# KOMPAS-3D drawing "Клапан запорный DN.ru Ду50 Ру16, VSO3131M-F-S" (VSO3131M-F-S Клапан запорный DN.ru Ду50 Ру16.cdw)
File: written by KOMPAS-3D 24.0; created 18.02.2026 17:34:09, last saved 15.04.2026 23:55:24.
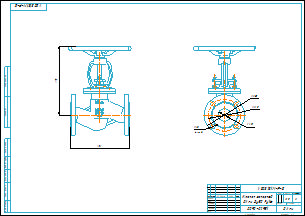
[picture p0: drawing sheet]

Document properties: Автор: R2D2; Форматы листов документа: A2; Полное имя файла: VSO3131M-F-S Клапан запорный DN.ru Ду50 Ру16.m3d; Масса: 10.5; Наименование: Клапан запорный DN.ru Ду50 Ру16; Количество листов документа: 1; Примечание: D090-02952

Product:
- Part/product: Клапан запорный DN.ru Ду50 Ру16  | designation VSO3131M-F-S
    Масса: 10.5
    Раздел спецификации: Прочие изделия
    Примечание: D090-02952

Views: Вид 1, Спереди, Проекционный вид 2
Referenced files in E:\Работа\Зайцев\VSO3131M-F-S Клапан запорный DN.ru Ду15-100 Ру40\DN50\: VSO3131M-F-S Клапан запорный DN.ru Ду50 Ру40.m3d
Referenced files in E:\Работа\Зайцев\VSO3131M-F-S Клапан запорный DN.ru Ду15-100 Ру16\DN50\: VSO3131M-F-S Клапан запорный DN.ru Ду50 Ру16.m3d
Referenced files in E:\Работа\Зайцев\Для компаса\: чертеж DN.ru А3.cdt
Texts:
  VSO3131M-F-S
  чертеж DN.ru А3.cdt
  Клапан запорный
  DN.ru Ду50 Ру16
  Клапан запорный DN.ru Ду50 Ру16
  VSO3131M-F-S Клапан запорный DN.ru Ду50 Ру16
Dimensions and other numbers on the sheet: 0; 3; 2; 4; 230; 270; 160; 125; 50; 18; 4 отв.; 1:2; 1; 10,5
